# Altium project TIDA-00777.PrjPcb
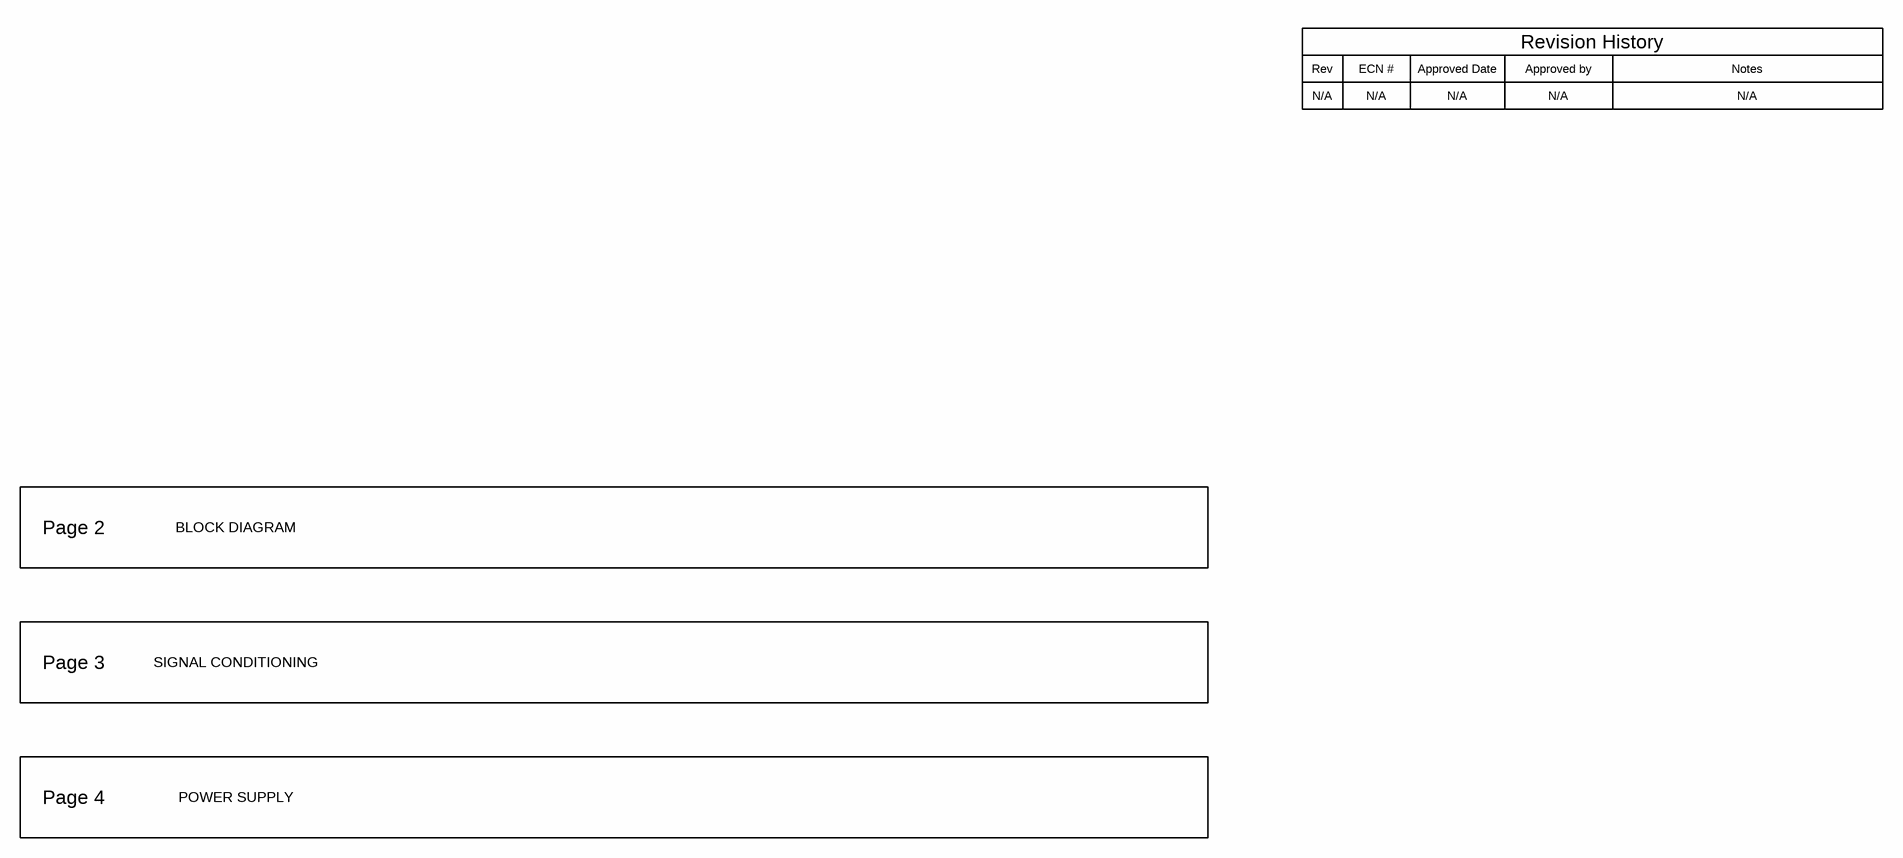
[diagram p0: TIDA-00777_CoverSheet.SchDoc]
EVM_Orderable: N/A; TID: TIDA-00777; TechSupport: http://www.ti.com/support; SCH_Rev: E2; PRJ_Title: Hardware Integrator AFE For Rogowski; PRJ_Number: TIDA-00777; PRJ_Engineer: Prahlad Supeda; PRJ_Customer: Public Release; PCB_Rev: E2; PCB_Layout: Manjunath M; CopyrightYear: 2016
5 sheets, 151 parts. Net scope: global (net labels, ports and power ports of the same name join across sheets).
Board file: TIDA-00777_PCB.PcbDoc
Sheets:
  TIDA-00777_CoverSheet.SchDoc
  TIDA-00777_BLOCK DIAGRAM.SchDoc
  TIDA-00777_SIGNAL CONDITIONING.SchDoc
  TIDA-00777_POWER SUPPLY.SchDoc
  TIDA-00777_EVM_Hardware.SchDoc

## Sheet TIDA-00777_CoverSheet.SchDoc: CoverSheet
size 431 x 279 mm; Date: Not shown in title block; ApprovedBy: Not shown in title block; CheckedBy: Not shown in title block; Author: Not shown in title block; CompanyName: Not shown in title block; DrawnBy: Prahlad Supeda; Engineer: Not shown in title block; Organization: Not shown in title block; Address1: Not shown in title block; Address2: Not shown in title block; Address3: Not shown in title block; Address4: Not shown in title block; DocumentNumber: 1; Revision: Use project parameter SCH_Rev; SheetNumber: 1; SheetTotal: 5; PageSetup: Record=PageOptions¦CenterHorizontal=True¦CenterVertical=True¦PrintScale=1.00¦XCorrection=1.00¦YCorrection=1.00¦PrintKind=0¦BorderSize=5000000¦LeftOffset=0¦BottomOffset=0¦Orientation=2¦PaperLength=1000¦PaperWidth=1000¦Scale=100¦PaperSource=15¦PrintQuality=600¦MediaType=1¦DitherType=10¦PaperKind=Letter¦PrintScaleMode=1

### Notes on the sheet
- Rev
- N/A
- ECN #
- Approved Date
- Approved by
- Revision History
- Notes
- Page 2
- BLOCK DIAGRAM
- Page 3
- SIGNAL CONDITIONING
- Page 4
- POWER SUPPLY

## Sheet TIDA-00777_BLOCK DIAGRAM.SchDoc: CoverSheet
size 431 x 279 mm; Date: Not shown in title block; ApprovedBy: Not shown in title block; CheckedBy: Not shown in title block; Author: Not shown in title block; CompanyName: Not shown in title block; DrawnBy: Prahlad Supeda; Engineer: Not shown in title block; Organization: Not shown in title block; Address1: Not shown in title block; Address2: Not shown in title block; Address3: Not shown in title block; Address4: Not shown in title block; DocumentNumber: 1; Revision: Use project parameter SCH_Rev; SheetNumber: 2; SheetTotal: 5; PageSetup: Record=PageOptions¦CenterHorizontal=True¦CenterVertical=True¦PrintScale=1.00¦XCorrection=1.00¦YCorrection=1.00¦PrintKind=0¦BorderSize=5000000¦LeftOffset=0¦BottomOffset=0¦Orientation=2¦PaperLength=1000¦PaperWidth=1000¦Scale=100¦PaperSource=15¦PrintQuality=600¦MediaType=1¦DitherType=10¦PaperKind=Letter¦PrintScaleMode=1
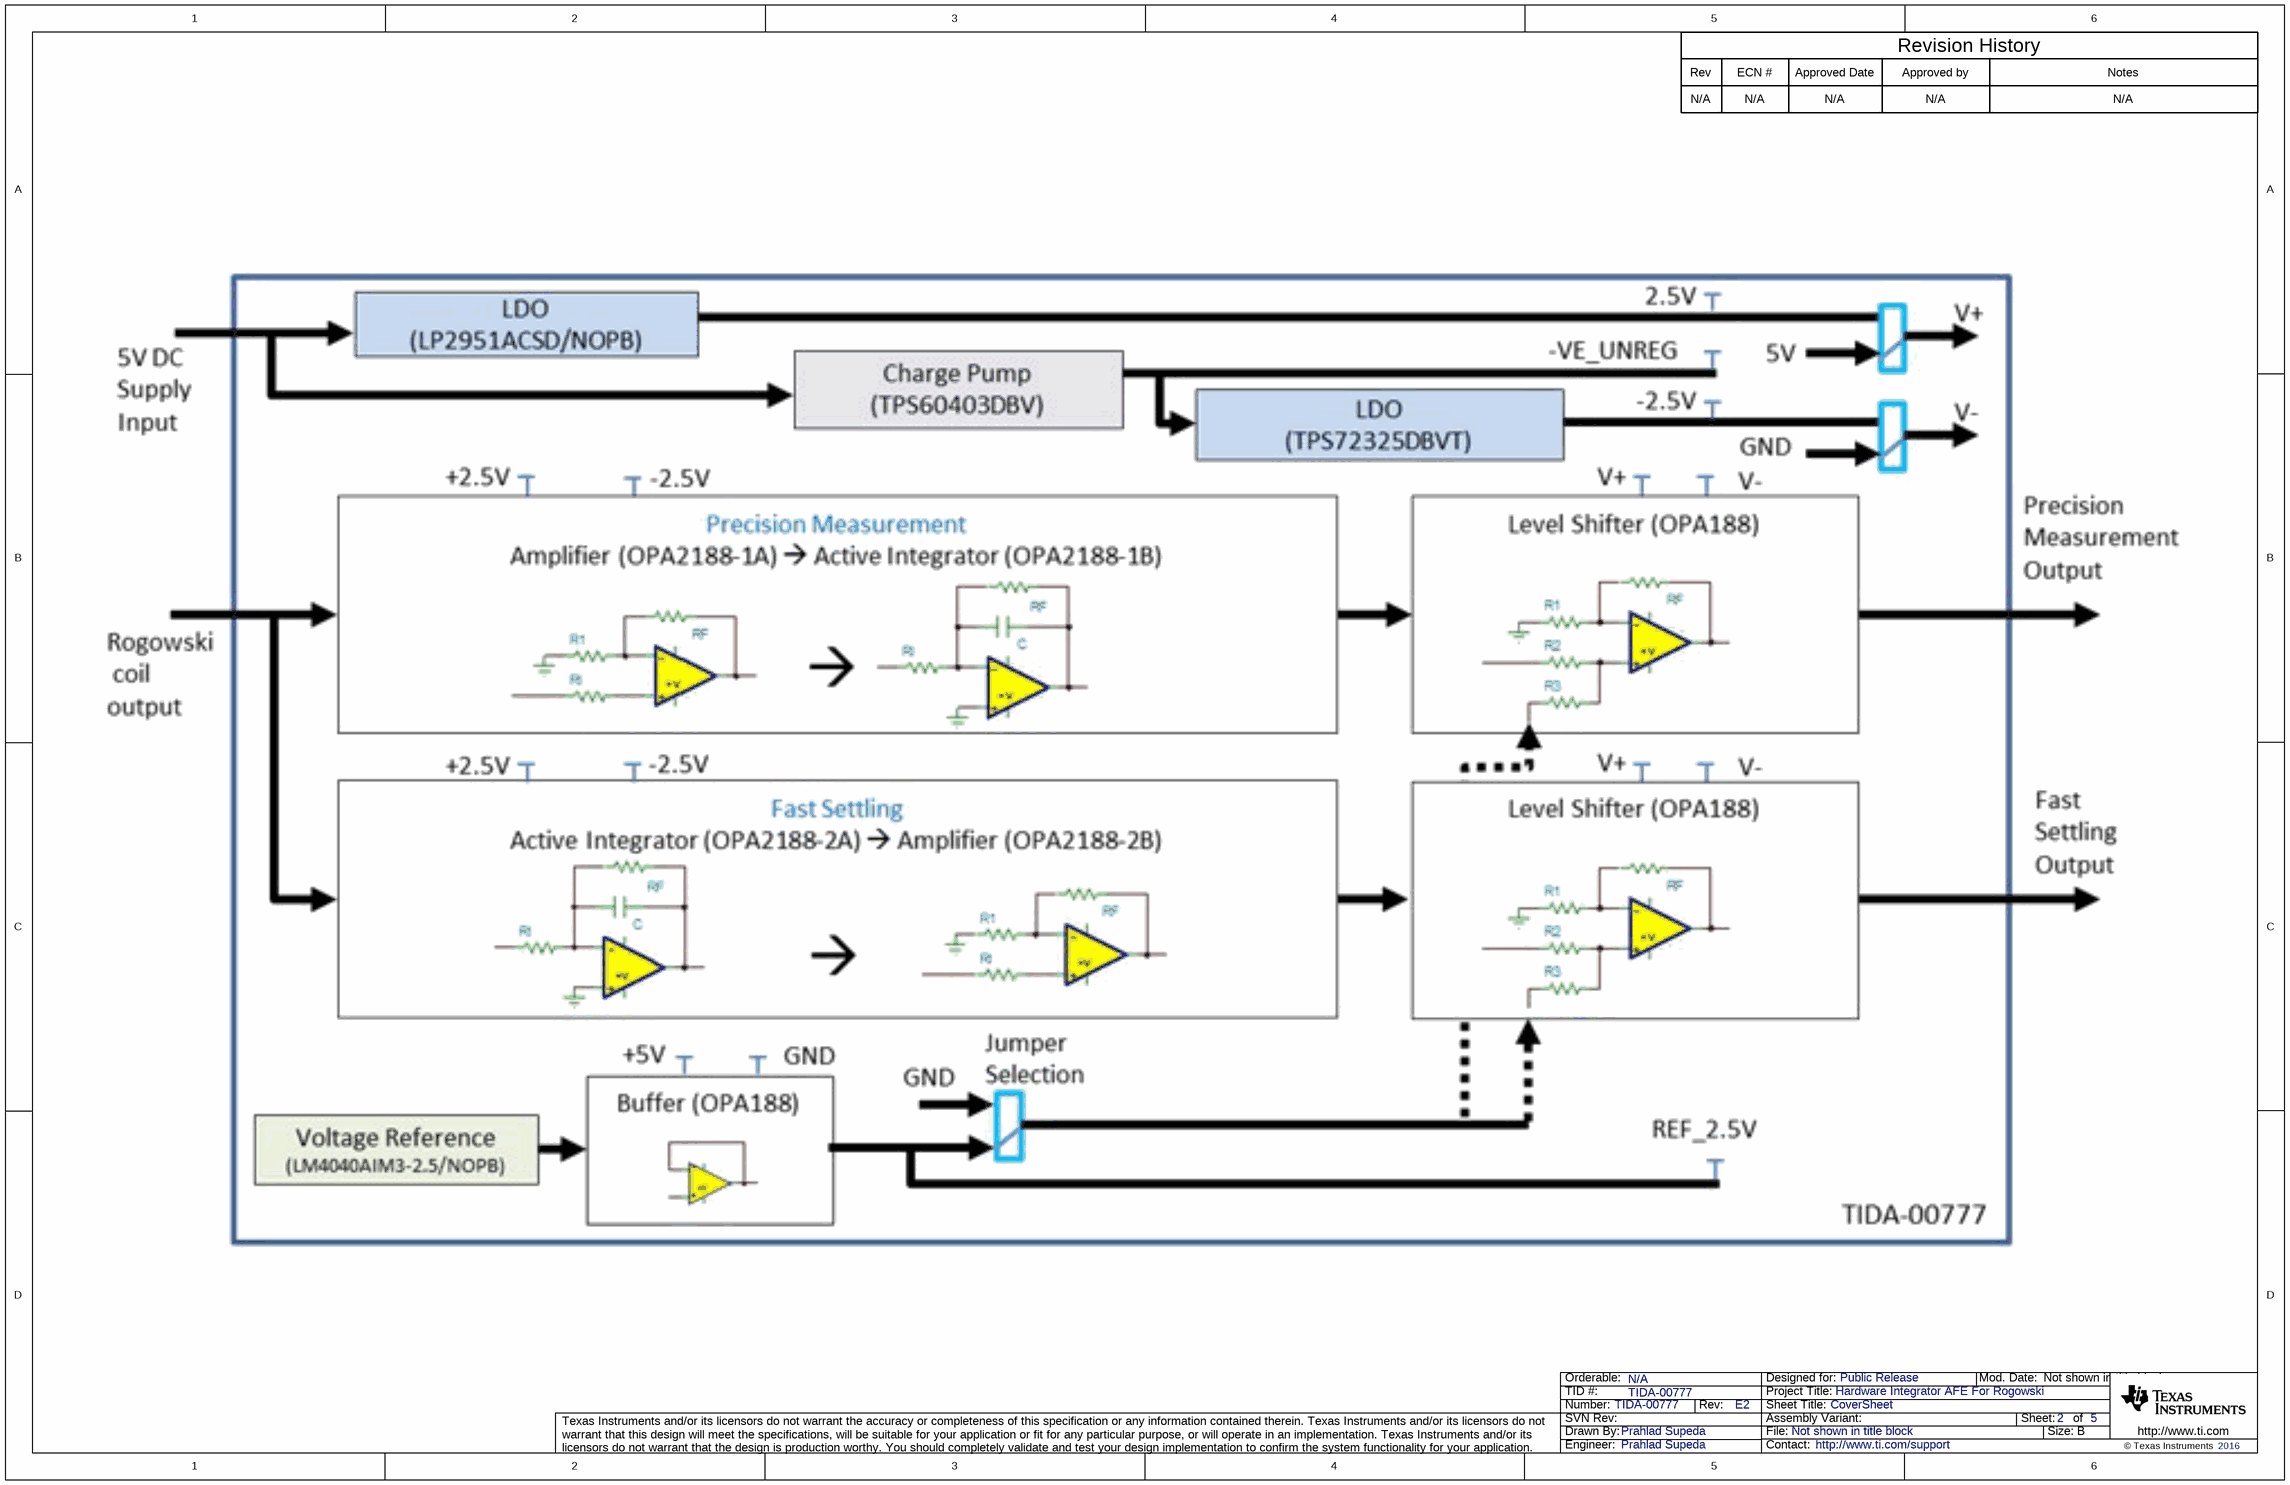
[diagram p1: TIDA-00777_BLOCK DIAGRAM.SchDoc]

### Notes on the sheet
- Rev
- N/A
- ECN #
- Approved Date
- Approved by
- Revision History
- Notes

## Sheet TIDA-00777_SIGNAL CONDITIONING.SchDoc: Signal Conditioning
size 431 x 279 mm; Date: Not shown in title block; ApprovedBy: Not shown in title block; CheckedBy: Not shown in title block; Author: Not shown in title block; CompanyName: Not shown in title block; DrawnBy: Prahlad Supeda; Engineer: Not shown in title block; Organization: Not shown in title block; Address1: Not shown in title block; Address2: Not shown in title block; Address3: Not shown in title block; Address4: Not shown in title block; DocumentNumber: 1; Revision: Use project parameter SCH_Rev; SheetNumber: 3; SheetTotal: 5; PageSetup: Record=PageOptions¦CenterHorizontal=True¦CenterVertical=True¦PrintScale=1.00¦XCorrection=1.00¦YCorrection=1.00¦PrintKind=0¦BorderSize=5000000¦LeftOffset=0¦BottomOffset=0¦Orientation=2¦PaperLength=1000¦PaperWidth=1000¦Scale=100¦PaperSource=15¦PrintQuality=600¦MediaType=1¦DitherType=10¦PaperKind=Letter¦PrintScaleMode=1
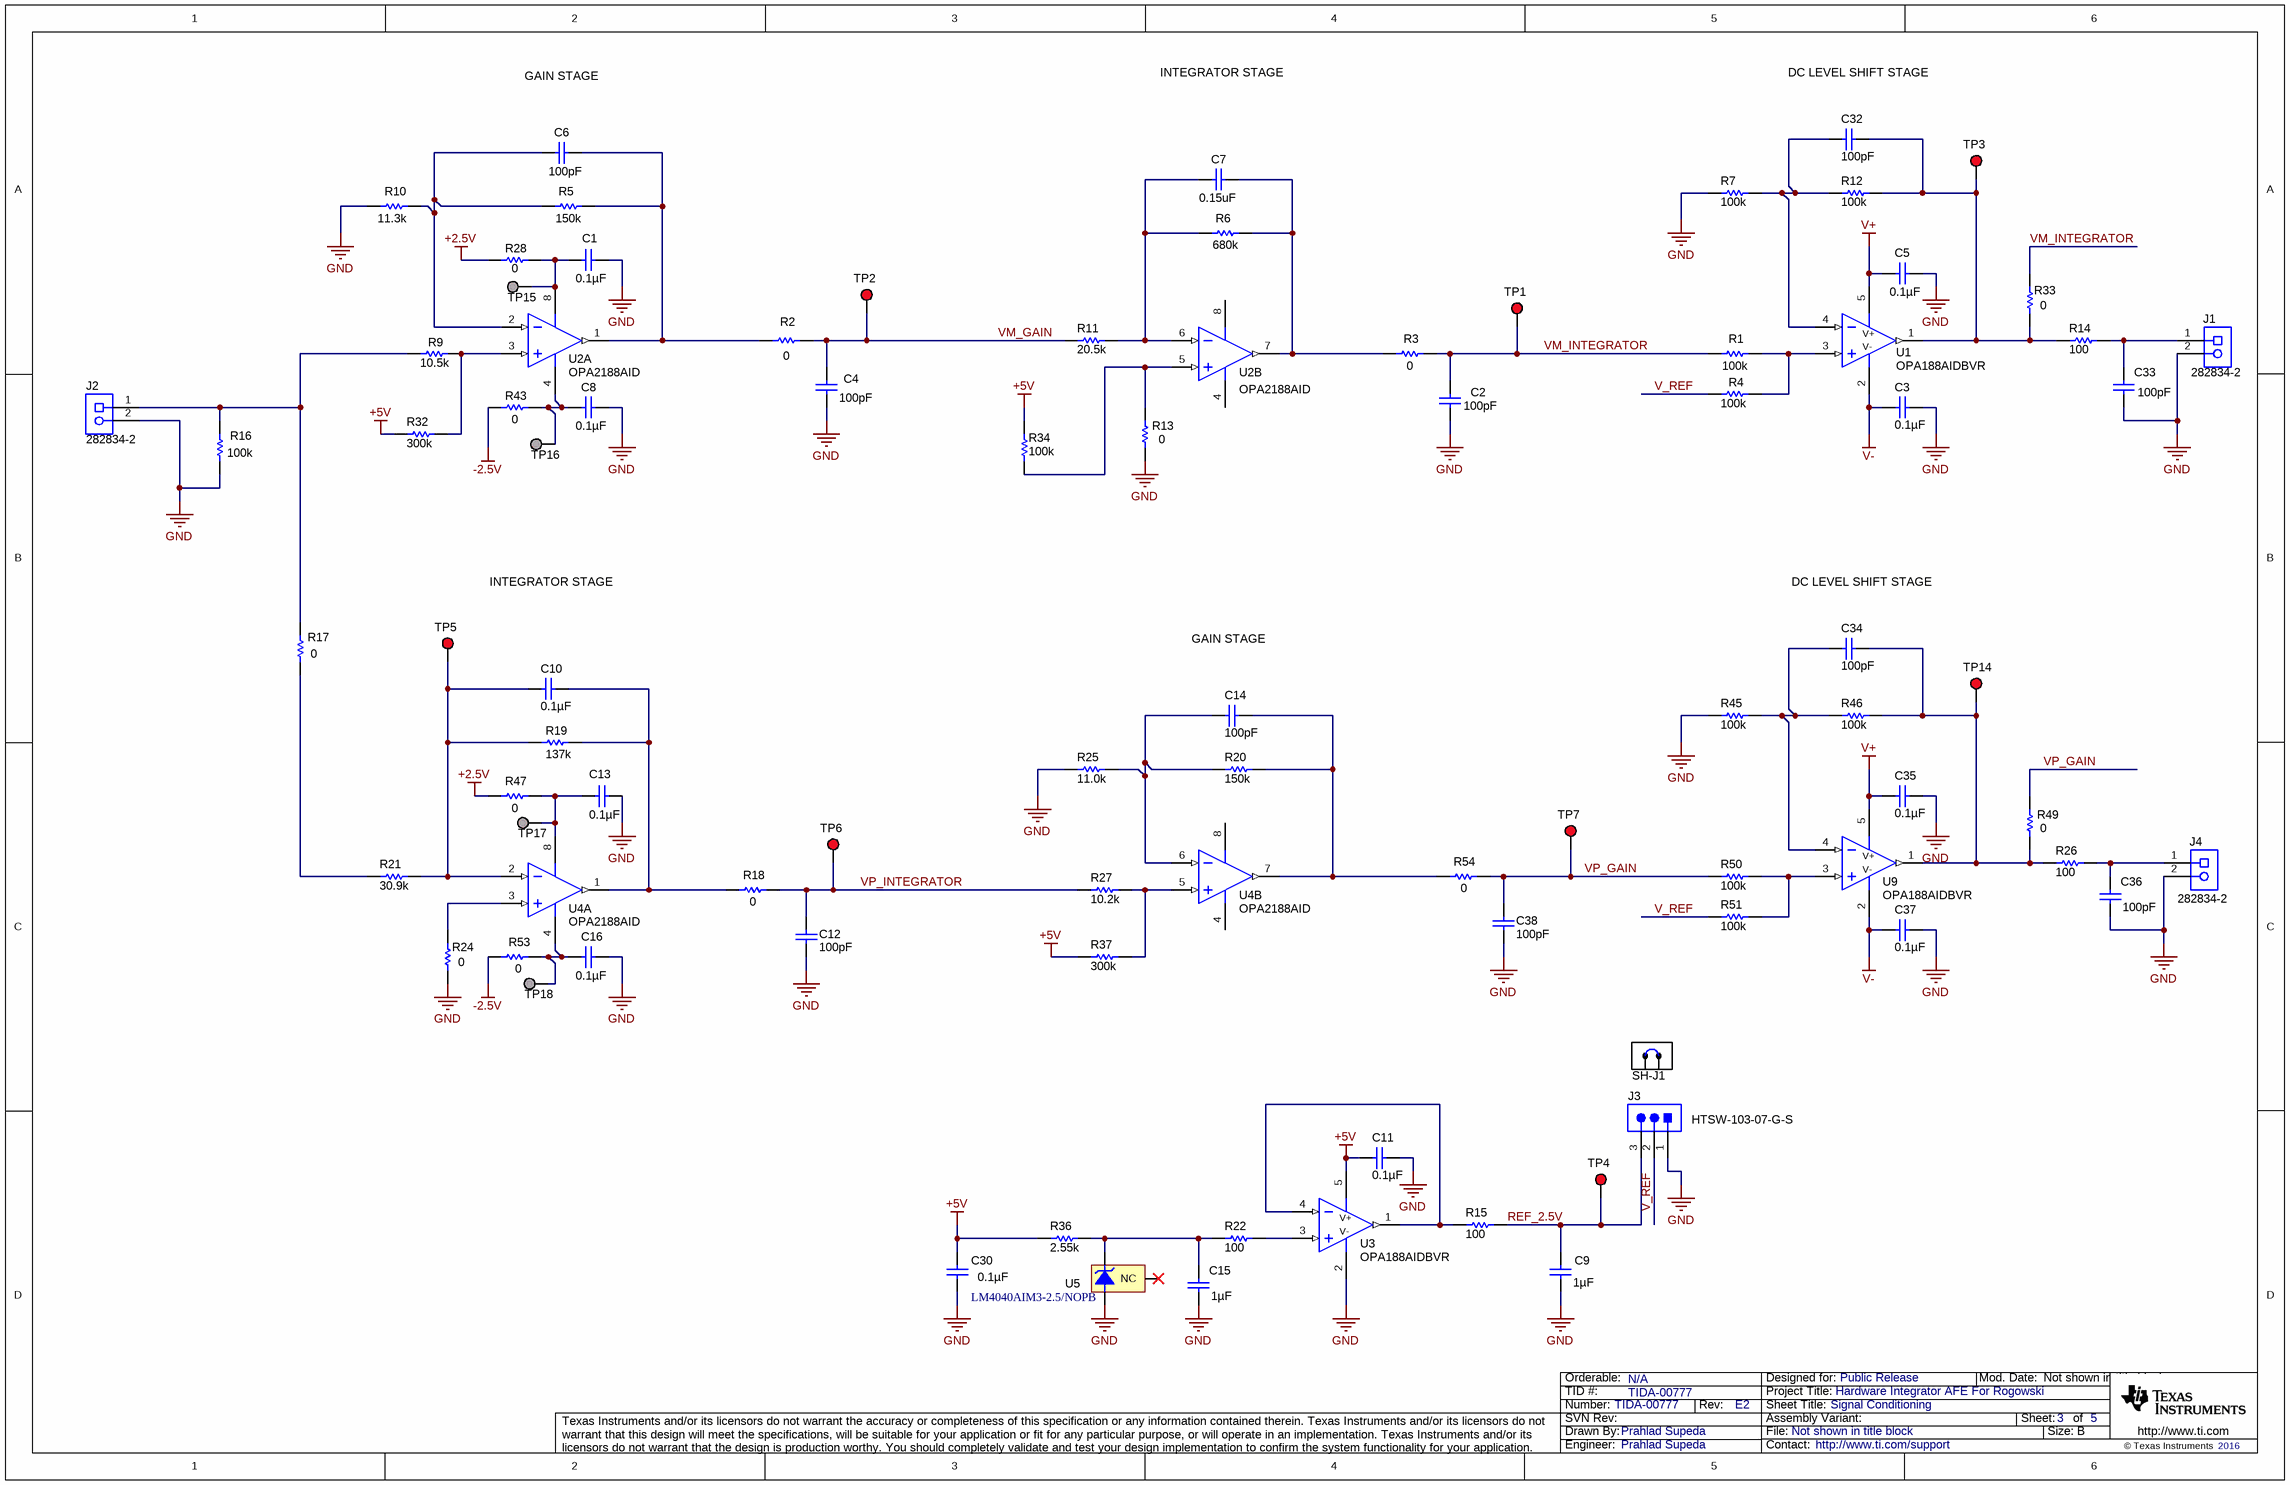
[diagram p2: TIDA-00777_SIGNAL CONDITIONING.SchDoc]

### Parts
C1  ValueDisplayed: 0.1µF  [0603]  (hidden comment: 06033C104JAT2A)
C2  ValueDisplayed: 100pF  [0603]  (hidden comment: 06035A101FAT2A)
C3  ValueDisplayed: 0.1µF  [0603]  (hidden comment: 06033C104JAT2A)
C4  ValueDisplayed: 100pF  [0603]  (hidden comment: 06035A101FAT2A)
C5  ValueDisplayed: 0.1µF  [0603]  (hidden comment: 06033C104JAT2A)
C6  ValueDisplayed: 100pF  [0603]  (hidden comment: 06035A101FAT2A)
C7  value 0.15uF  [B32529_730x250x650]  (hidden comment: B32529C154J289)
C8  ValueDisplayed: 0.1µF  [0603]  (hidden comment: 06033C104JAT2A)
C9  ValueDisplayed: 1µF  [0805_HV]  (hidden comment: GRM21BR71H105KA12L)
C10  ValueDisplayed: 0.1µF  [R82_720x250x650]  (hidden comment: R82DC3100DQ50J)
C11  ValueDisplayed: 0.1µF  [0603]  (hidden comment: 06033C104JAT2A)
C12  ValueDisplayed: 100pF  [0603]  (hidden comment: 06035A101FAT2A)
C13  ValueDisplayed: 0.1µF  [0603]  (hidden comment: 06033C104JAT2A)
C14  ValueDisplayed: 100pF  [0603]  (hidden comment: 06035A101FAT2A)
C15  ValueDisplayed: 1µF  [0805_HV]  (hidden comment: GRM21BR71H105KA12L)
C16  ValueDisplayed: 0.1µF  [0603]  (hidden comment: 06033C104JAT2A)
C30  ValueDisplayed: 0.1µF  [0603]  (hidden comment: 06033C104JAT2A)
C32  ValueDisplayed: 100pF  [0603]  (hidden comment: 06035A101FAT2A)
C33  ValueDisplayed: 100pF  [0603]  (hidden comment: 06035A101FAT2A)
C34  ValueDisplayed: 100pF  [0603]  (hidden comment: 06035A101FAT2A)
C35  ValueDisplayed: 0.1µF  [0603]  (hidden comment: 06033C104JAT2A)
C36  ValueDisplayed: 100pF  [0603]  (hidden comment: 06035A101FAT2A)
C37  ValueDisplayed: 0.1µF  [0603]  (hidden comment: 06033C104JAT2A)
C38  ValueDisplayed: 100pF  [0603]  (hidden comment: 06035A101FAT2A)
J1  282834-2  [TEC_282834-2]
J2  282834-2  [TEC_282834-2]
J3  HTSW-103-07-G-S  [Samtec_HTSW-103-07-G-S]
J4  282834-2  [TEC_282834-2]
R1  ValueDisplayed: 100k  [0603]  (hidden comment: RG1608P-104-B-T5)
R2  ValueDisplayed: 0  [0603]  (hidden comment: RC0603JR-070RL)
R3  ValueDisplayed: 0  [0603]  (hidden comment: RC0603JR-070RL)
R4  ValueDisplayed: 100k  [0603]  (hidden comment: RG1608P-104-B-T5)
R5  ValueDisplayed: 150k  [0603]  (hidden comment: RG1608P-154-B-T5)
R6  ValueDisplayed: 680k  [0603]  (hidden comment: CPF0603B680KE1)
R7  ValueDisplayed: 100k  [0603]  (hidden comment: RG1608P-104-B-T5)
R9  ValueDisplayed: 10.5k  [0603]  (hidden comment: RG1608P-1052-B-T5)
R10  ValueDisplayed: 11.3k  [0603]  (hidden comment: RG1608P-1132-B-T5)
R11  ValueDisplayed: 20.5k  [0603]  (hidden comment: RP73PF1J20K5BTDF)
R12  ValueDisplayed: 100k  [0603]  (hidden comment: RG1608P-104-B-T5)
R13  ValueDisplayed: 0  [0603]  (hidden comment: RC0603JR-070RL)
R14  ValueDisplayed: 100  [0603]  (hidden comment: RG1608P-101-B-T5)
R15  ValueDisplayed: 100  [0603]  (hidden comment: CRCW0603100RFKEA)
R16  ValueDisplayed: 100k  [0603]  (hidden comment: CRCW0603100KFKEA)
R17  ValueDisplayed: 0  [0603]  (hidden comment: RC0603JR-070RL)
R18  ValueDisplayed: 0  [0603]  (hidden comment: RC0603JR-070RL)
R19  ValueDisplayed: 137k  [0603]  (hidden comment: ERA-3AEB1373V)
R20  ValueDisplayed: 150k  [0603]  (hidden comment: CRCW0603150KFKEA)
R21  ValueDisplayed: 30.9k  [0603]  (hidden comment: RC0603FR-0730K9L)
R22  ValueDisplayed: 100  [0603]  (hidden comment: CRCW0603100RFKEA)
R24  ValueDisplayed: 0  [0603]  (hidden comment: RC0603JR-070RL)
R25  ValueDisplayed: 11.0k  [0603]  (hidden comment: CRCW060311K0FKEA)
R26  ValueDisplayed: 100  [0603]  (hidden comment: CRCW0603100RFKEA)
R27  ValueDisplayed: 10.2k  [0603]  (hidden comment: RG1608P-1022-B-T5)
R28  ValueDisplayed: 0  [0603]  (hidden comment: RC0603JR-070RL)
R32  ValueDisplayed: 300k  [0603]  (hidden comment: CRCW0603300KFKEA)
R33  ValueDisplayed: 0  [0603]  (hidden comment: RC0603JR-070RL)
R34  ValueDisplayed: 100k  [0603]  (hidden comment: CRCW0603100KFKEA)
R36  ValueDisplayed: 2.55k  [0603]  (hidden comment: CRCW06032K55FKEA)
R37  ValueDisplayed: 300k  [0603]  (hidden comment: CRCW0603300KFKEA)
R43  ValueDisplayed: 0  [0603]  (hidden comment: RC0603JR-070RL)
R45  ValueDisplayed: 100k  [0603]  (hidden comment: CRCW0603100KFKEA)
R46  ValueDisplayed: 100k  [0603]  (hidden comment: CRCW0603100KFKEA)
R47  ValueDisplayed: 0  [0603]  (hidden comment: RC0603JR-070RL)
R49  ValueDisplayed: 0  [0603]  (hidden comment: RC0603JR-070RL)
R50  ValueDisplayed: 100k  [0603]  (hidden comment: CRCW0603100KFKEA)
R51  ValueDisplayed: 100k  [0603]  (hidden comment: CRCW0603100KFKEA)
R53  ValueDisplayed: 0  [0603]  (hidden comment: RC0603JR-070RL)
R54  ValueDisplayed: 0  [0603]  (hidden comment: RC0603JR-070RL)
SH-J1  881545-2  [TE_881545-2]  (value not drawn)  (mechanical)
TP1  5000  [Keystone5000]  (value not drawn)
TP2  5000  [Keystone5000]  (value not drawn)
TP3  5000  [Keystone5000]  (value not drawn)
TP4  5000  [Keystone5000]  (value not drawn)
TP5  5000  [Keystone5000]  (value not drawn)
TP6  5000  [Keystone5000]  (value not drawn)
TP7  5000  [Keystone5000]  (value not drawn)
TP14  5000  [Keystone5000]  (value not drawn)
TP15  TESTPOINT  [TP_H045P075]  (value not drawn)  (no BOM)
TP16  TESTPOINT  [TP_H045P075]  (value not drawn)  (no BOM)
TP17  TESTPOINT  [TP_H045P075]  (value not drawn)  (no BOM)
TP18  TESTPOINT  [TP_H045P075]  (value not drawn)  (no BOM)
U1  OPA188AIDBVR  [DBV0005A_N]
U2  OPA2188AID  [D0008A_N]  (parts A,B of 2)
U3  OPA188AIDBVR  [DBV0005A_N]
U4  OPA2188AID  [D0008A_N]  (parts A,B of 2)
U5  LM4040AIM3-2.5/NOPB  [MF03A_N]
U9  OPA188AIDBVR  [DBV0005A_N]

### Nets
+2.5V: R28.1 R47.1
+5V: C11.2 C30.2 R32.1 R34.2 R36.1 R37.1 U3.5(V+)
-2.5V: R43.1 R53.1
GND: C1.1 C2.2 C3.1 C4.2 C5.1 C8.1 C9.2 C11.1 C12.2 C13.1 C15.2 C16.1 C30.1 C33.1 C35.1 C36.1 C37.1 C38.2 J1.2 J2.2 J3.1 J4.2 R7.1 R10.1 R13.1 R16.1 R24.1 R25.1 R45.1 U3.2(V-) U5.2(-V)
V+: C5.2 C35.2 U1.5(V+) U9.5(V+)
V-: C3.2 C37.2 U1.2(V-) U9.2(V-)
REF_2.5V: C9.1 J3.3 R15.2 TP4.1
V_REF: J3.2 R4.1 R51.1
VM_GAIN: C4.1 R2.2 R11.1 TP2.1
VM_INTEGRATOR: C2.1 R1.1 R3.2 R33.1 TP1.1
VP_GAIN: C38.1 R49.1 R50.1 R54.2 TP7.1
VP_INTEGRATOR: C12.1 R18.2 R27.1 TP6.1
NetC1_2: C1.2 R28.2 TP15.1 U2.8(V+)
NetC6_1: C6.1 R5.1 R10.2 U2.2(IN_A-)
NetC6_2: C6.2 R2.1 R5.2 U2.1(OUT_A)
NetC7_1: C7.1 R3.1 R6.2 U2.7(OUT_B)
NetC7_2: C7.2 R6.1 R11.2 U2.6(IN_B-)
NetC8_2: C8.2 R43.2 TP16.1 U2.4(V-)
NetC10_1: C10.1 R18.1 R19.2 U4.1(OUT_A)
NetC10_2: C10.2 R19.1 R21.2 TP5.1 U4.2(IN_A-)
NetC13_2: C13.2 R47.2 TP17.1 U4.8(V+)
NetC14_1: C14.1 R20.1 R25.2 U4.6(IN_B-)
NetC14_2: C14.2 R20.2 R54.1 U4.7(OUT_B)
NetC15_1: C15.1 R22.1 R36.2 U5.1(+V)
NetC16_2: C16.2 R53.2 TP18.1 U4.4(V-)
NetC32_1: C32.1 R7.2 R12.1 U1.4(IN-)
NetC32_2: C32.2 R12.2 R14.1 R33.2 TP3.1 U1.1(OUT)
NetC33_2: C33.2 J1.1 R14.2
NetC34_1: C34.1 R45.2 R46.1 U9.4(IN-)
NetC34_2: C34.2 R26.1 R46.2 R49.2 TP14.1 U9.1(OUT)
NetC36_2: C36.2 J4.1 R26.2
NetJ2_1: J2.1 R9.1 R16.2 R17.2
NetR1_2: R1.2 R4.2 U1.3(IN+)
NetR9_2: R9.2 R32.2 U2.3(IN_A+)
NetR13_2: R13.2 R34.1 U2.5(IN_B+)
NetR15_1: R15.1 U3.1(OUT) U3.4(IN-)
NetR17_1: R17.1 R21.1
NetR22_2: R22.2 U3.3(IN+)
NetR24_2: R24.2 U4.3(IN_A+)
NetR27_2: R27.2 R37.2 U4.5(IN_B+)
NetR50_2: R50.2 R51.2 U9.3(IN+)

Not connected (* = marked no-connect by the designer): U5 3(NC)*

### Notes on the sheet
- GAIN STAGE
- INTEGRATOR STAGE
- DC LEVEL SHIFT STAGE

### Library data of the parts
C1 C3 C5 C8 C11 C13 C16 C30 C35 C37 = 06033C104JAT2A: CAP, CERM, 0.1 µF, 25 V, +/- 5%, X7R, 0603; Manufacturer: AVX; Polarized: N; CompType: Capacitor; Value: 0.1uF; U/M: EA; Cap_F: 0.0000001; Tolerance_%: 5; ESR_ohm: 0.05; Value1: 0.05 ohm; VDC_V: 25; Value2: 25V; TaMin_C: -55; TaMax_C: 125; AEC Category: Q200
C2 C4 C6 C12 C14 C32-C34 C36 C38 = 06035A101FAT2A: CAP, CERM, 100 pF, 50 V, +/- 1%, C0G/NP0, 0603; Manufacturer: AVX; Polarized: N; CompType: Capacitor; Value: 100pF; U/M: EA; Cap_F: 0.0000000001; Tolerance_%: 1; Value1: Unknown; VDC_V: 50; Value2: 50V; TaMin_C: -55; TaMax_C: 125; AEC Category: Q200
C7 = B32529C154J289: CAP, FILM, 0.15uF, 63VDC, 5%, RADIAL-2P; Manufacturer: TDK; CompType: Film Capacitor; SymbolCreator: x0199378
C9 C15 = GRM21BR71H105KA12L: CAP, CERM, 1 µF, 50 V, +/- 10%, X7R, 0805; Manufacturer: MuRata; Polarized: N; CompType: Capacitor; Value: 1uF; U/M: EA; Cap_F: 0.000001; Tolerance_%: 10; Value1: Unknown; VDC_V: 50; Value2: 50V; TaMin_C: -55; TaMax_C: 125; Cap_Case: 0805; AEC Category: Q200
C10 = R82DC3100DQ50J: CAP, Film, 0.1 µF, 63 V, +/- 5%, TH; Manufacturer: Kemet; Polarized: N; CompType: Capacitor; Value: 0.1uF; U/M: EA; Cap_F: 0.0000001; Tolerance_%: 5; Value1: Unknown; VDC_V: 63; Value2: 63V; TaMin_C: -55; TaMax_C: 105; Cap_Case: 7.2x2.5x6.5mm; AEC Category: Q200
J1 J2 J4 = 282834-2: Terminal Block, 2x1, 2.54mm, TH; Manufacturer: TE Connectivity; SymbolCreator: a0412235
J3 = HTSW-103-07-G-S: Header, 100mil, 3x1, Gold, TH; Manufacturer: Samtec; SymbolCreator: a0799628
R1 R4 R7 R12 = RG1608P-104-B-T5: RES, 100 k, 0.1%, 0.1 W, 0603; Manufacturer: Susumu Co Ltd; CompType: Resistor; Value: 100k; Res_ohm: 100000; Tolerance_%: 0.1; Value2: 0.1W; VDC_V: 75; TempCo: 25 ppm/C; EIA_Code: E192; U/M: EA; AEC Category: Q200
R2 R3 R13 R17 R18 R24 R28 R33 R43 R47 R49 R53 R54 = RC0603JR-070RL: RES, 0, 5%, 0.1 W, 0603; Manufacturer: Yageo America; CompType: Resistor; Value: 0; Value_Code: 0000; Tolerance_%: 5; Power_W: 0.1; Value2: 0.1W; VDC_V: 50; TempCo: 200 ppm/C; EIA_Code: E24; U/M: EA; AEC Category: Q200
R5 = RG1608P-154-B-T5: RES, 150 k, 0.1%, 0.1 W, 0603; Manufacturer: Susumu Co Ltd; CompType: Resistor; Value: 150k; Res_ohm: 150000; Tolerance_%: 0.1; Value2: 0.1W; VDC_V: 75; TempCo: 25 ppm/C; EIA_Code: E192; U/M: EA; AEC Category: Q200
R6 = RC0603FR-07680KL: RES SMD 680K OHM 0.1% 1/16W 0603; Manufacturer: TE Connectivity AMP Connectors; CompType: Resistor; Res_ohm: 680000; Tolerance_%: 1; Value1: 1%; Power_W: 0.1; Value2: 0.1W; VDC_V: 150; TempCo: 200 ppm/C; U/M: EA; AEC Category: Q200
R9 = RG1608P-1052-B-T5: RES, 10.5 k, 0.1%, 0.1 W, 0603; Manufacturer: Susumu Co Ltd; CompType: Resistor; Value: 10.5k; Res_ohm: 10500; Value_Code: 10k5; Tolerance_%: 0.1; Value2: 0.1W; VDC_V: 75; TempCo: 25 ppm/C; EIA_Code: E192; U/M: EA; AEC Category: Q200
R10 = RG1608P-1132-B-T5: RES, 11.3 k, 0.1%, 0.1 W, 0603; Manufacturer: Susumu Co Ltd; CompType: Resistor; Value: 11.3k; Res_ohm: 11300; Value_Code: 11k3; Tolerance_%: 0.1; Value2: 0.1W; VDC_V: 75; TempCo: 25 ppm/C; EIA_Code: E192; U/M: EA; AEC Category: Q200
R11 = CRCW060320K5FKEA: RES SMD 20.5K OHM 0.1% 1/6W 0603; Manufacturer: TE Connectivity AMP Connectors; CompType: Resistor; Res_ohm: 20500; Value_Code: 20k5; Tolerance_%: 1; Value1: 1%; Power_W: 0.1; Value2: 0.1W; VDC_V: 75; TempCo: 100 ppm/C; EIA_Code: E96; U/M: EA; AEC Category: Q200
R14 = RG1608P-101-B-T5: RES, 100, 0.1%, 0.1 W, 0603; Manufacturer: Susumu Co Ltd; CompType: Resistor; Value: 100; Value_Code: 100R; Tolerance_%: 0.1; Value2: 0.1W; VDC_V: 75; TempCo: 25 ppm/C; EIA_Code: E192; U/M: EA; AEC Category: Q200
R15 R22 R26 = CRCW0603100RFKEA: RES, 100, 1%, 0.1 W, 0603; Manufacturer: Vishay-Dale; CompType: Resistor; Value: 100; Value_Code: 100R; Tolerance_%: 1; Power_W: 0.1; Value2: 0.1W; VDC_V: 75; TempCo: 100 ppm/C; EIA_Code: E96; U/M: EA; AEC Category: Q200
R16 R34 R45 R46 R50 R51 = CRCW0603100KFKEA: RES, 100 k, 1%, 0.1 W, 0603; Manufacturer: Vishay-Dale; CompType: Resistor; Value: 100k; Res_ohm: 100000; Tolerance_%: 1; Power_W: 0.1; Value2: 0.1W; VDC_V: 75; TempCo: 100 ppm/C; EIA_Code: E96; U/M: EA; AEC Category: Q200
R19 = RT0603BRD07137KL: RES SMD 137K OHM 0.1% 1/10W 0603; Manufacturer: Panasonic Electronic Components; CompType: Resistor; Res_ohm: 137000; Tolerance_%: 0.1; Value2: 0.1W; VDC_V: 75; TempCo: 25 ppm/C; EIA_Code: E192; U/M: EA; AEC Category: Q200
R20 = CRCW0603150KFKEA: RES, 150 k, 1%, 0.1 W, 0603; Manufacturer: Vishay-Dale; CompType: Resistor; Value: 150k; Res_ohm: 150000; Tolerance_%: 1; Power_W: 0.1; Value2: 0.1W; VDC_V: 75; TempCo: 100 ppm/C; EIA_Code: E96; U/M: EA; AEC Category: Q200
R21 = RC0603FR-0730K9L: RES, 30.9 k, 1%, 0.1 W, 0603; Manufacturer: Yageo America; CompType: Resistor; Value: 30.9k; Res_ohm: 30900; Value_Code: 30k9; Tolerance_%: 1; Power_W: 0.1; Value2: 0.1W; VDC_V: 150; TempCo: 200 ppm/C; EIA_Code: E96; U/M: EA; AEC Category: Q200
R25 = CRCW060311K0FKEA: RES, 11.0 k, 1%, 0.1 W, 0603; Manufacturer: Vishay-Dale; CompType: Resistor; Value: 11.0k; Res_ohm: 11000; Value_Code: 11k0; Tolerance_%: 1; Power_W: 0.1; Value2: 0.1W; VDC_V: 75; TempCo: 100 ppm/C; EIA_Code: E96; U/M: EA; AEC Category: Q200
R27 = RG1608P-1022-B-T5: RES, 10.2 k, 0.1%, 0.1 W, 0603; Manufacturer: Susumu Co Ltd; CompType: Resistor; Value: 10.2k; Res_ohm: 10200; Value_Code: 10k2; Tolerance_%: 0.1; Value2: 0.1W; VDC_V: 75; TempCo: 25 ppm/C; EIA_Code: E192; U/M: EA; AEC Category: Q200
R32 R37 = CRCW0603300KFKEA: RES, 300 k, 1%, 0.1 W, 0603; Manufacturer: Vishay-Dale; CompType: Resistor; Value: 300k; Res_ohm: 300000; Tolerance_%: 1; Power_W: 0.1; Value2: 0.1W; TempCo: 100 ppm/C; U/M: EA; AEC Category: Q200
R36 = CRCW06032K55FKEA: RES, 2.55 k, 1%, 0.1 W, 0603; Manufacturer: Vishay-Dale; CompType: Resistor; Value: 2.55k; Res_ohm: 2550; Value_Code: 2k55; Tolerance_%: 1; Power_W: 0.1; Value2: 0.1W; VDC_V: 75; TempCo: 100 ppm/C; EIA_Code: E96; U/M: EA; AEC Category: Q200
SH-J1 = 881545-2: Shunt, 100mil, Gold plated, Black; Manufacturer: TE Connectivity
TP1-TP7 TP14 = 5000: Test Point, Miniature, Red, TH; Manufacturer: Keystone; CompType: Test Point Loop; ContactFinish: Silver
TP15-TP18 = TP_H0.45P0.75: Manufacturer: Texas Instruments; CompType: Pad
U1 U3 U9 = OPA188AIDBVR: Precision, Low-Noise, Rail-to-Rail Output, 36 V, Zero-Drift Operational Amplifiers, DBV0005A; Alternate PartNumber: OPA188AIDBVT; Manufacturer: Texas Instruments; CompType: IC; U/M: EA
U2 U4 = OPA2188AID: 0.03 uV/degC, 6 uV Vos, Low Noise, Rail-to-Rail Output, Zero-Drift Operational Amplifier, 4 to 36 V, -40 to 105 degC, 8-pin SOIC (D0008A), Green (RoHS & no Sb/Br); Manufacturer: Texas Instruments; Alternate PartNumber: Equivalent; CMRR(Min)(dB): 120; GBW(Typ)(MHz): 2; IIB(Max)(pA): 850; Iq per channel(Max)(mA): 0.475; Offset Drift(Typ)(uV/C): 0.03; Packing: TUBE; Rating: Catalog; Slew Rate(Typ)(V/us): 0.8; Sub Family: High Supply Voltage Amplifier (>=30V), Low Noise Amp (<=10nV/rtHz), Low Offset Voltage Amplifier (<=500uV), Low Power Amp (<=500uA), Precision Amplifier, Zero Drift Precision Amplifier; Total Supply Voltage(Max)(+5V is 5, +/-5V is 10): 36; Total Supply Voltage(Min)(+5V is 5, +/-5V is 10): 4; Vio (25C)(Max)(mV): 0.025
U5 = LM4040AIM3-2.5/NOPB: Precision Micropower Shunt Voltage Reference, 3-pin SOT-23, Pb-Free; Manufacturer: Texas Instruments; PackageTopMarking: R2A*XTT; PowerWise: N; CompType: Voltage Reference IC

## Sheet TIDA-00777_POWER SUPPLY.SchDoc: Power Supply
size 431 x 279 mm; Date: Not shown in title block; ApprovedBy: Not shown in title block; CheckedBy: Not shown in title block; Author: Not shown in title block; CompanyName: Not shown in title block; DrawnBy: Prahlad Supeda; Engineer: Not shown in title block; Organization: Not shown in title block; Address1: Not shown in title block; Address2: Not shown in title block; Address3: Not shown in title block; Address4: Not shown in title block; DocumentNumber: 1; Revision: Use project parameter SCH_Rev; SheetNumber: 4; SheetTotal: 5; PageSetup: Record=PageOptions¦CenterHorizontal=True¦CenterVertical=True¦PrintScale=1.00¦XCorrection=1.00¦YCorrection=1.00¦PrintKind=0¦BorderSize=5000000¦LeftOffset=0¦BottomOffset=0¦Orientation=2¦PaperLength=1000¦PaperWidth=1000¦Scale=100¦PaperSource=15¦PrintQuality=600¦MediaType=1¦DitherType=10¦PaperKind=Letter¦PrintScaleMode=1
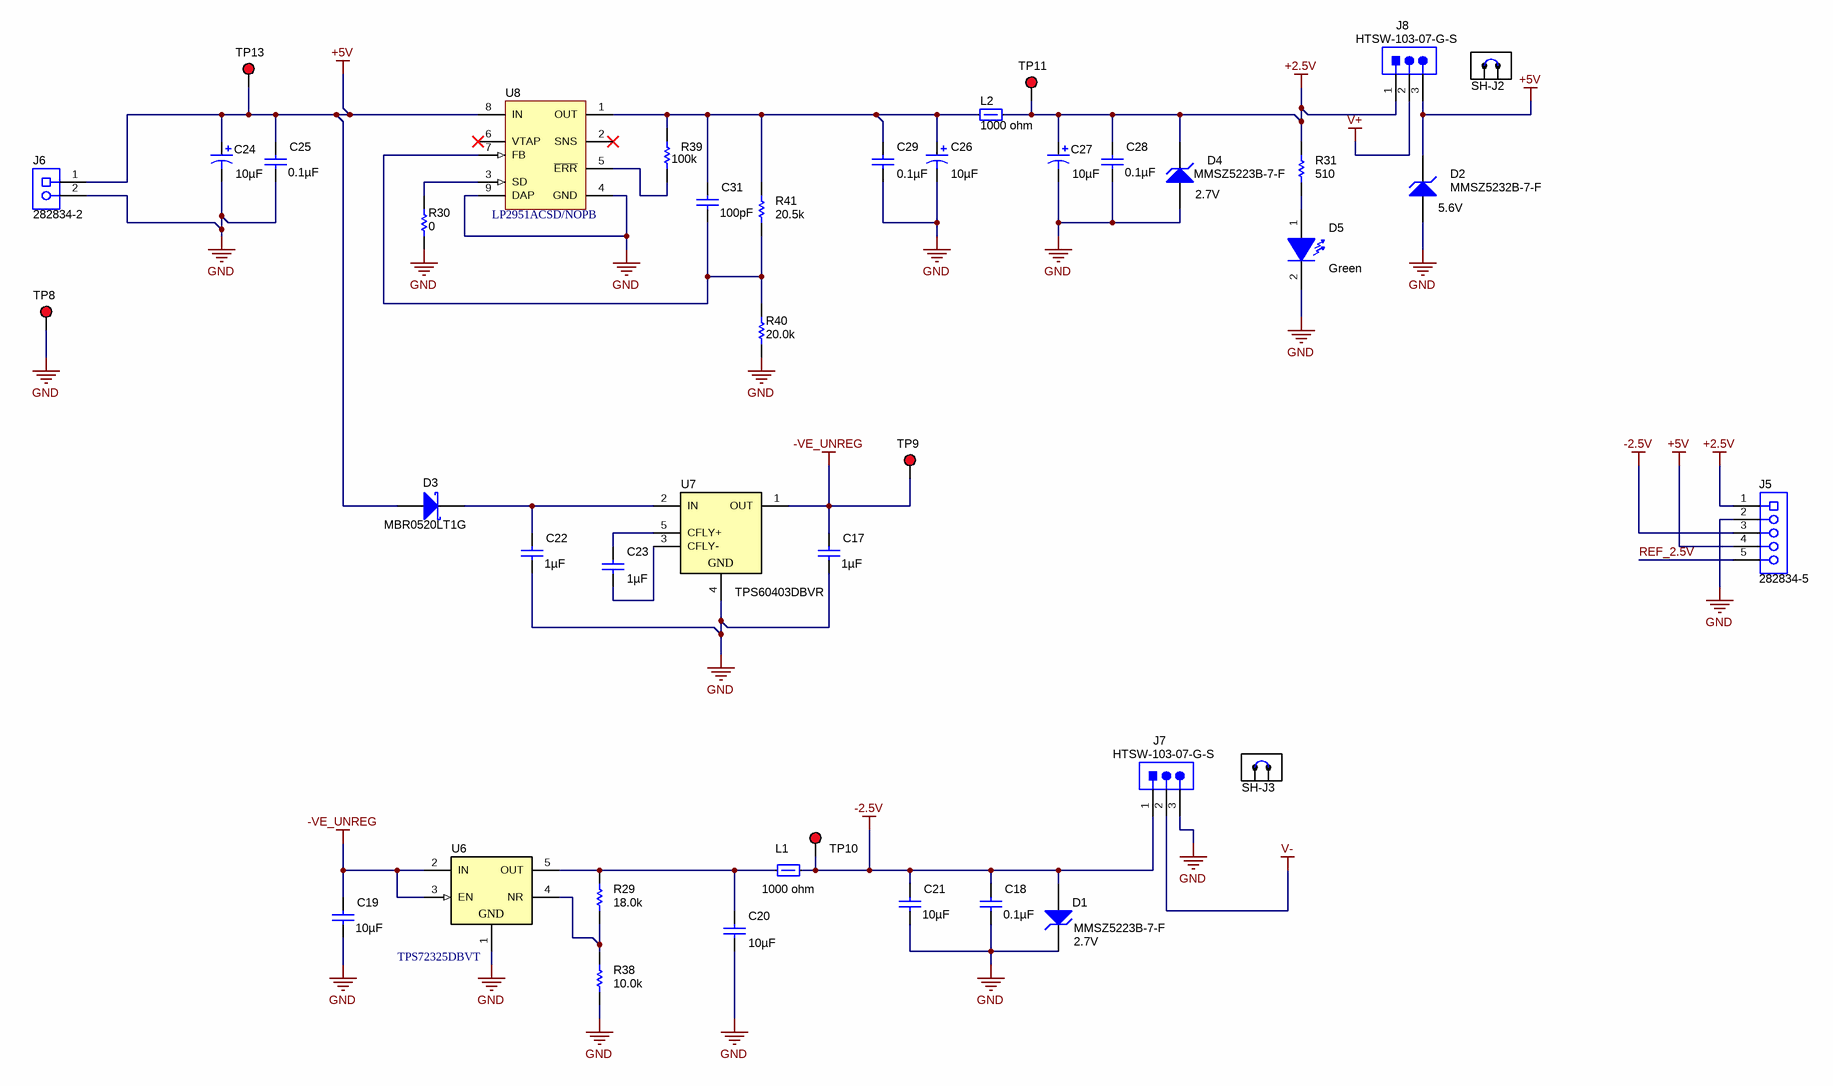
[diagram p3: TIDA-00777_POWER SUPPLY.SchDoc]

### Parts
C17  ValueDisplayed: 1µF  [0805_HV]  (hidden comment: GRM21BR71H105KA12L)
C18  ValueDisplayed: 0.1µF  [0603]  (hidden comment: 06033C104JAT2A)
C19  ValueDisplayed: 10µF  [1210_280]  (hidden comment: 12103C106KAT2A)
C20  ValueDisplayed: 10µF  [1210_280]  (hidden comment: 12103C106KAT2A)
C21  ValueDisplayed: 10µF  [1210_280]  (hidden comment: 12103C106KAT2A)
C22  ValueDisplayed: 1µF  [0805_HV]  (hidden comment: GRM21BR71H105KA12L)
C23  ValueDisplayed: 1µF  [0805_HV]  (hidden comment: GRM21BR71H105KA12L)
C24  ValueDisplayed: 10µF  [6032-28]  (hidden comment: 293D106X9025C2TE3)
C25  ValueDisplayed: 0.1µF  [0603]  (hidden comment: 06033C104JAT2A)
C26  ValueDisplayed: 10µF  [6032-28]  (hidden comment: 293D106X9025C2TE3)
C27  ValueDisplayed: 10µF  [6032-28]  (hidden comment: 293D106X9025C2TE3)
C28  ValueDisplayed: 0.1µF  [0603]  (hidden comment: 06033C104JAT2A)
C29  ValueDisplayed: 0.1µF  [0603]  (hidden comment: 06033C104JAT2A)
C31  ValueDisplayed: 100pF  [0603]  (hidden comment: 06035A101FAT2A)
D1  MMSZ5223B-7-F  value 2.7V  [SOD-123]
D2  MMSZ5232B-7-F  value 5.6V  [SOD-123]
D3  MBR0520LT1G  [SOD-123]
D4  MMSZ5223B-7-F  value 2.7V  [SOD-123]
D5  value Green  [LG L29K_GREEN]  (hidden comment: LG L29K-G2J1-24-Z)
J5  282834-5  [TE_282834-5]
J6  282834-2  [TEC_282834-2]
J7  HTSW-103-07-G-S  [Samtec_HTSW-103-07-G-S]
J8  HTSW-103-07-G-S  [Samtec_HTSW-103-07-G-S]
L1  value 1000 ohm  [MMZ1608_095]  (hidden comment: MMZ1608B102CTA00)
L2  value 1000 ohm  [MMZ1608_095]  (hidden comment: MMZ1608B102CTA00)
R29  ValueDisplayed: 18.0k  [0603]  (hidden comment: CRCW060318K0FKEA)
R30  ValueDisplayed: 0  [0603]  (hidden comment: RC0603JR-070RL)
R31  ValueDisplayed: 510  [0603]  (hidden comment: RC0603FR-07510RL)
R38  ValueDisplayed: 10.0k  [0603]  (hidden comment: RC0603FR-0710KL)
R39  ValueDisplayed: 100k  [0603]  (hidden comment: CRCW0603100KFKEA)
R40  ValueDisplayed: 20.0k  [0603]  (hidden comment: RC0603FR-0720KL)
R41  ValueDisplayed: 20.5k  [0603]  (hidden comment: RC0603FR-0720K5L)
SH-J2  881545-2  [TE_881545-2]  (value not drawn)  (mechanical)
SH-J3  881545-2  [TE_881545-2]  (value not drawn)  (mechanical)
TP8  5000  [Keystone5000]  (value not drawn)
TP9  5000  [Keystone5000]  (value not drawn)
TP10  5000  [Keystone5000]  (value not drawn)
TP11  5000  [Keystone5000]  (value not drawn)
TP13  5000  [Keystone5000]  (value not drawn)
U6  TPS72325DBVT  [DBV0005A_N]
U7  TPS60403DBVR  [DBV0005A_N]
U8  LP2951ACSD/NOPB  [SDC08A]

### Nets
+2.5V: C27.1(+) C28.1 D4.1(K) J5.1 J8.1 L2.2 R31.2 TP11.1
+5V: C24.1(+) C25.1 D2.1(K) D3.2(A) J5.4 J6.1 J8.3 TP13.1 U8.8(IN)
-2.5V: C18.1 C21.1 D1.2(A) J5.3 J7.1 L1.2 TP10.1
-VE_UNREG: C17.1 C19.1 TP9.1 U6.2(IN) U6.3(EN) U7.1(OUT)
GND: C17.2 C18.2 C19.2 C20.2 C21.2 C22.2 C24.2(-) C25.2 C26.2(-) C27.2(-) C28.2 C29.2 D1.1(K) D2.2(A) D4.2(A) D5.2(K) J5.2 J6.2 J7.3 R30.1 R38.1 R40.1 TP8.1 U6.1(GND) U7.4(GND) U8.4(GND) U8.9(DAP)
V+: J8.2
V-: J7.2
REF_2.5V: J5.5
NetC20_1: C20.1 L1.1 R29.2 U6.5(OUT)
NetC22_1: C22.1 D3.1(K) U7.2(IN)
NetC23_1: C23.1 U7.3(CFLY-)
NetC23_2: C23.2 U7.5(CFLY+)
NetC26_1: C26.1(+) C29.1 C31.1 L2.1 R39.2 R41.2 U8.1(OUT)
NetC31_2: C31.2 R40.2 R41.1 U8.7(FB)
NetD5_1: D5.1(A) R31.1
NetR29_1: R29.1 R38.2 U6.4(NR)
NetR30_2: R30.2 U8.3(SD)
NetR39_1: R39.1 U8.5(~{ERR})

Not connected (* = marked no-connect by the designer): U8 2(SNS)* 6(VTAP)*

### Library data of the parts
C17 C22 C23 = GRM21BR71H105KA12L: as C9 on sheet TIDA-00777_SIGNAL CONDITIONING
C18 C25 C28 C29 = 06033C104JAT2A: as C1 on sheet TIDA-00777_SIGNAL CONDITIONING
C19-C21 = 12103C106KAT2A: CAP, CERM, 10 µF, 25 V, +/- 10%, X7R, 1210; Manufacturer: AVX; Polarized: N; CompType: Capacitor; Value: 10uF; U/M: EA; Cap_F: 0.00001; Tolerance_%: 10; Value1: Unknown; VDC_V: 25; Value2: 25V; TaMin_C: -55; TaMax_C: 125; Cap_Case: 1210; AEC Category: Q200
C24 C26 C27 = 293D106X9025C2TE3: CAP, TA, 10 µF, 25 V, +/- 10%, 1.5 ohm, SMD; Manufacturer: Vishay-Sprague; Polarized: Y; CompType: Capacitor; Value: 10uF; U/M: EA; Cap_F: 0.00001; Tolerance_%: 10; Value1: 1.5 ohm; VDC_V: 25; Value2: 25V; ESR_ohm: 1.5; IRMS_A: 0.27; TaMin_C: -55; TaMax_C: 125; Cap_Case: C; AEC Category: Q200
C31 = 06035A101FAT2A: as C2 on sheet TIDA-00777_SIGNAL CONDITIONING
D1 D4 = MMSZ5223B-7-F: Diode, Zener, 2.7 V, 500 mW, SOD-123; Manufacturer: Diodes Inc.; SymbolCreator: a0412235; U/M: EA; Power_W: 0.5; Vz_V: 2.7; Value1: 0.5W; RJA_CperW: 350; AEC Category: Q101
D2 = MMSZ5232B-7-F: Diode, Zener, 5.6 V, 500 mW, SOD-123; Manufacturer: Diodes Inc.; SymbolCreator: a0412235; U/M: EA; Power_W: 0.5; Vz_V: 5.6; Value1: 0.5W; RJA_CperW: 350; AEC Category: Q101
D3 = MBR0520LT1G: Diode, Schottky, 20 V, 0.5 A, SOD-123; Manufacturer: ON Semiconductor; U/M: EA; Vf_V: 0.385; Value: 20V; Value1: 0.5A; Value2: 0.385V; Io_A: 0.5; Vr_V: 20; TJmax_C: 125; RJC_CperW: 150; AEC Category: Q101
D5 = LG L29K-G2J1-24-Z: LED, Green, SMD; Manufacturer: OSRAM; Vf_V: 1.7; Value2: 1.7V; Io_A: 0.002; Tjmax_C: 110; Value1: W; U/M: EA
J5 = 282834-5: Terminal Block, 2.54mm, 5 Pos, Tin, Green, R/A, TH; Manufacturer: TE Connectivity; SymbolCreator: a0412235; Pitch_mm: 2.54; Gender: Female; Row_Count: 1; Current_A: 10; Voltage_V: 150
J6 = 282834-2: as J1 on sheet TIDA-00777_SIGNAL CONDITIONING
J7 J8 = HTSW-103-07-G-S: as J3 on sheet TIDA-00777_SIGNAL CONDITIONING
L1 L2 = MMZ1608B102CTA00: Ferrite Bead, 1000 ohm @ 100 MHz, 0.3 A, 0603; Manufacturer: TDK; Imax_A: 0.3; DCR_ohm: 0.6; Value1: 0.6 ohm; Value2: 0.3A; ZTyp@100MHz_Ohm: 1000
R29 = RC0603FR-0718KL: RES, 18.0 k, 1%, 0.1 W, 0603; Manufacturer: Vishay; CompType: Resistor; Value: 18.0k; Res_ohm: 18000; Value_Code: 18k0; Tolerance_%: 1; Power_W: 0.1; Value2: 0.1W; VDC_V: 150; TempCo: 200 ppm/C; U/M: EA; AEC Category: Q200
R30 = RC0603JR-070RL: as R2 on sheet TIDA-00777_SIGNAL CONDITIONING
R31 = RC0603FR-07510RL: RES, 510, 1%, 0.1 W, 0603; Manufacturer: Yageo America; CompType: Resistor; Value: 510; Value_Code: 510R; Tolerance_%: 1; Power_W: 0.1; Value2: 0.1W; VDC_V: 150; TempCo: 200 ppm/C; U/M: EA; AEC Category: Q200
R38 = RC0603FR-0710KL: RES, 10.0 k, 1%, 0.1 W, 0603; Manufacturer: Yageo America; CompType: Resistor; Value: 10.0k; Res_ohm: 10000; Value_Code: 10k0; Tolerance_%: 1; Power_W: 0.1; Value2: 0.1W; VDC_V: 150; TempCo: 200 ppm/C; EIA_Code: E96; U/M: EA; AEC Category: Q200
R39 = CRCW0603100KFKEA: as R16 on sheet TIDA-00777_SIGNAL CONDITIONING
R40 = RC0603FR-0720KL: RES, 20.0 k, 1%, 0.1 W, 0603; Manufacturer: Yageo America; CompType: Resistor; Value: 20.0k; Res_ohm: 20000; Value_Code: 20k0; Tolerance_%: 1; Power_W: 0.1; Value2: 0.1W; VDC_V: 150; TempCo: 200 ppm/C; EIA_Code: E96; U/M: EA; AEC Category: Q200
R41 = RC0603FR-0720K5L: RES, 20.5 k, 1%, 0.1 W, 0603; Manufacturer: Yageo America; CompType: Resistor; Value: 20.5k; Res_ohm: 20500; Value_Code: 20k5; Tolerance_%: 1; Power_W: 0.1; Value2: 0.1W; VDC_V: 150; TempCo: 200 ppm/C; EIA_Code: E96; U/M: EA; AEC Category: Q200
SH-J2 SH-J3 = 881545-2: as SH-J1 on sheet TIDA-00777_SIGNAL CONDITIONING
TP8-TP11 TP13 = 5000: as TP1 on sheet TIDA-00777_SIGNAL CONDITIONING
U6 = TPS72325DBVT: Single Output High PSRR LDO, 200 mA, Fixed -2.5 V Output, -10 to -2.7 V Input, 5-pin SOT-23 (DBV), -40 to 125 degC, Green (RoHS & no Sb/Br); Manufacturer: Texas Instruments; Alternate PartNumber: Equivalent; Accuracy(%): 2; Iout(Max)(A): 0.2; Iq(Typ)(mA): 0.13; SubFamily: Single Channel LDO; Vdo(Typ)(mV): 280
U7 = TPS60403DBVR: -1.8 to -5.25 V, Inverting Charge Pump Regulator, 60 mA, 1.8 to 5.25 V Input with 2-Cell Alkaline / Nixx Input, -40 to 85 degC, 5-pin SOT23 (DBV5), Green (RoHS & no Sb/Br); Manufacturer: Texas Instruments; Alternate PartNumber: Equivalent; 2-Cell Alkaline/Nixx Input: TRUE; Efficiency(Typ)(%): 99; Iout(Max)(A): 0.06; Iq(Typ)(mA): 0.425; Switching Frequency(Max)(kHz): 300; Topology: Inverting Buck/Boost; Vin(Max)(V): 5.25; Vin(Min)(V): 1.8
U8 = LP2951ACSD/NOPB: Series of Adjustable Micropower Voltage Regulators, 8-pin LLP, Pb-Free; Manufacturer: Texas Instruments; PackageTopMarking: NS*UZXYTT*2951AC; PowerWise: N; CompType: LDO IC

## Sheet TIDA-00777_EVM_Hardware.SchDoc: EVM_Hardware
size 431 x 279 mm; Date: Not shown in title block; ApprovedBy: Not shown in title block; CheckedBy: Not shown in title block; Author: Not shown in title block; CompanyName: Not shown in title block; DrawnBy: Prahlad Supeda; Engineer: Not shown in title block; Organization: Not shown in title block; Address1: Not shown in title block; Address2: Not shown in title block; Address3: Not shown in title block; Address4: Not shown in title block; DocumentNumber: 1; Revision: Use project parameter SCH_Rev; SheetNumber: 5; SheetTotal: 5; PageSetup: Record=PageOptions¦CenterHorizontal=True¦CenterVertical=True¦PrintScale=1.00¦XCorrection=1.00¦YCorrection=1.00¦PrintKind=0¦BorderSize=5000000¦LeftOffset=0¦BottomOffset=0¦Orientation=2¦PaperLength=1000¦PaperWidth=1000¦Scale=100¦PaperSource=15¦PrintQuality=600¦MediaType=1¦DitherType=10¦PaperKind=Letter¦PrintScaleMode=1
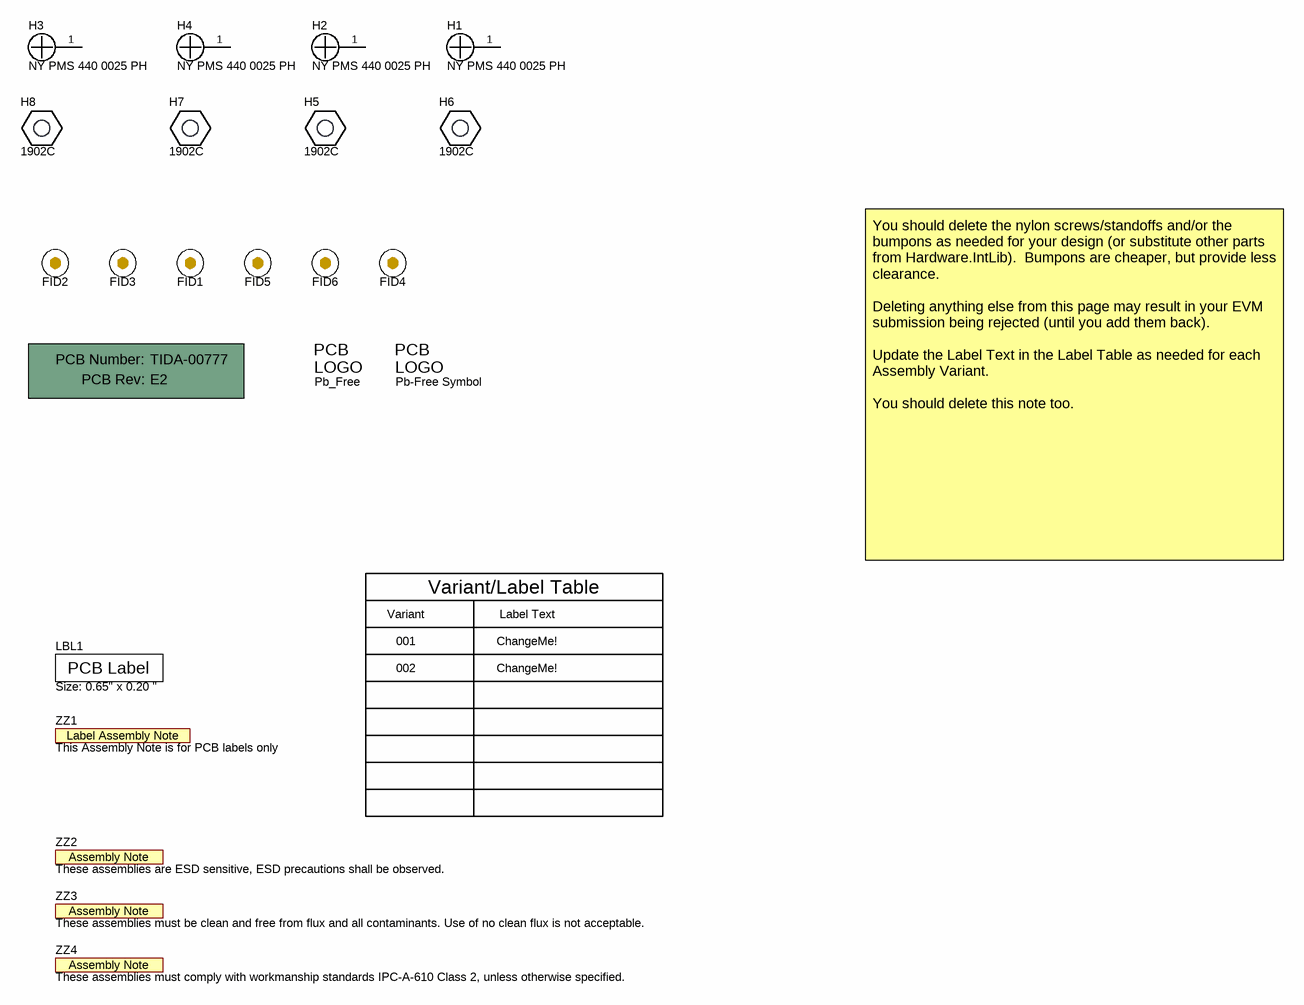
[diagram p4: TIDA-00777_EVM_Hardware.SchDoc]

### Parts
!PCB1  Printed Circuit Board  (value not drawn)  (mechanical)
FID1  Fiducial  [Fiducial10-20]  (value not drawn)
FID2  Fiducial  [Fiducial10-20]  (value not drawn)
FID3  Fiducial  [Fiducial10-20]  (value not drawn)
FID4  Fiducial  [Fiducial10-20]  (value not drawn)
FID5  Fiducial  [Fiducial10-20]  (value not drawn)
FID6  Fiducial  [Fiducial10-20]  (value not drawn)
H1  NY PMS 440 0025 PH  [NY PMS 440 0025 PH]
H2  NY PMS 440 0025 PH  [NY PMS 440 0025 PH]
H3  NY PMS 440 0025 PH  [NY PMS 440 0025 PH]
H4  NY PMS 440 0025 PH  [NY PMS 440 0025 PH]
H5  1902C  [Keystone_1902C]
H6  1902C  [Keystone_1902C]
H7  1902C  [Keystone_1902C]
H8  1902C  [Keystone_1902C]
LBL1  Size: 0.65" x 0.20 "  [Label_650x200]
Logo3  Pb-Free Symbol  [Pb-Free_Overlay_Small]  (no BOM)
Pb_Free  ESD Susceptible  [ESD_Overlay_small]  (value not drawn)  (no BOM)
ZZ1  This Assembly Note is for PCB labels only  [AssemblyNoteLabel]  (no BOM)
ZZ2  These assemblies are ESD sensitive, ESD precautions shall be observed.  [AssemblyNote]  (no BOM)
ZZ3  These assemblies must be clean and free from flux and all contaminants. Use of no clean flux is not acceptable.  [AssemblyNote]  (no BOM)
ZZ4  These assemblies must comply with workmanship standards IPC-A-610 Class 2, unless otherwise specified.  [AssemblyNote]  (no BOM)

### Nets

Not connected (* = marked no-connect by the designer): H1 1; H2 1; H3 1; H4 1

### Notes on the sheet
- Variant
- Variant/Label Table
- Label Text
- You should delete the nylon screws/standoffs and/or the bumpons as needed for your design (or substitute other parts from Hardware.IntLib).  Bumpons are cheaper, but provide less clearance.
  Deleting anything else from this page may result in your EVM submission being rejected (until you add them back).
  Update the Label Text in the Label Table as needed for each Assembly Variant.
  You should delete this note too.
- 001
- 002
- ChangeMe!

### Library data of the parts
!PCB1 = PCB: Manufacturer: Any; PartNumber: TIDA-00777; SymbolCreator: a0412235
FID1-FID6 = Fiducial: Fiducial mark.  There is nothing to buy or mount.; SymbolCreator: codlsc
H1-H4 = NY PMS 440 0025 PH: Machine Screw, Round, #4-40 x 1/4, Nylon, Philips panhead; Manufacturer: B&F Fastener Supply; CompType: Hardware; SymbolCreator: codlsc; U/M: EA
H5-H8 = 1902C: Standoff, Hex, 0.5"L #4-40 Nylon; Manufacturer: Keystone; CompType: Hardware
LBL1 = THT-14-423-10: Thermal Transfer Printable Labels, 0.650" W x 0.200" H - 10,000 per roll; Manufacturer: Brady; SymbolCreator: a0412235; CompType: Label
Logo3 = Pb-Free: SymbolCreator: a0412235
Pb_Free = ESD_Susceptible: ESD Susceptible Symbol; SymbolCreator: a0412235
ZZ1 = AssemblyNoteLabel: SymbolCreator: a0412235
ZZ2-ZZ4 = AssemblyNote: SymbolCreator: codlsc

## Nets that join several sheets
+2.5V: TIDA-00777_SIGNAL CONDITIONING (R28.1 R47.1), TIDA-00777_POWER SUPPLY (8 pins)
+5V: TIDA-00777_SIGNAL CONDITIONING (7 pins), TIDA-00777_POWER SUPPLY (9 pins)
-2.5V: TIDA-00777_SIGNAL CONDITIONING (R43.1 R53.1), TIDA-00777_POWER SUPPLY (7 pins)
GND: TIDA-00777_SIGNAL CONDITIONING (31 pins), TIDA-00777_POWER SUPPLY (27 pins)
V+: TIDA-00777_SIGNAL CONDITIONING (C5.2 C35.2 U1.5 U9.5), TIDA-00777_POWER SUPPLY (J8.2)
V-: TIDA-00777_SIGNAL CONDITIONING (C3.2 C37.2 U1.2 U9.2), TIDA-00777_POWER SUPPLY (J7.2)
REF_2.5V: TIDA-00777_SIGNAL CONDITIONING (C9.1 J3.3 R15.2 TP4.1), TIDA-00777_POWER SUPPLY (J5.5)

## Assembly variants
001: not fitted C2 C4 C12 C38 FID1 FID2 FID3 LBL1 R16 R29 R30 R32 R33 R34 R37 R38 R39 R49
